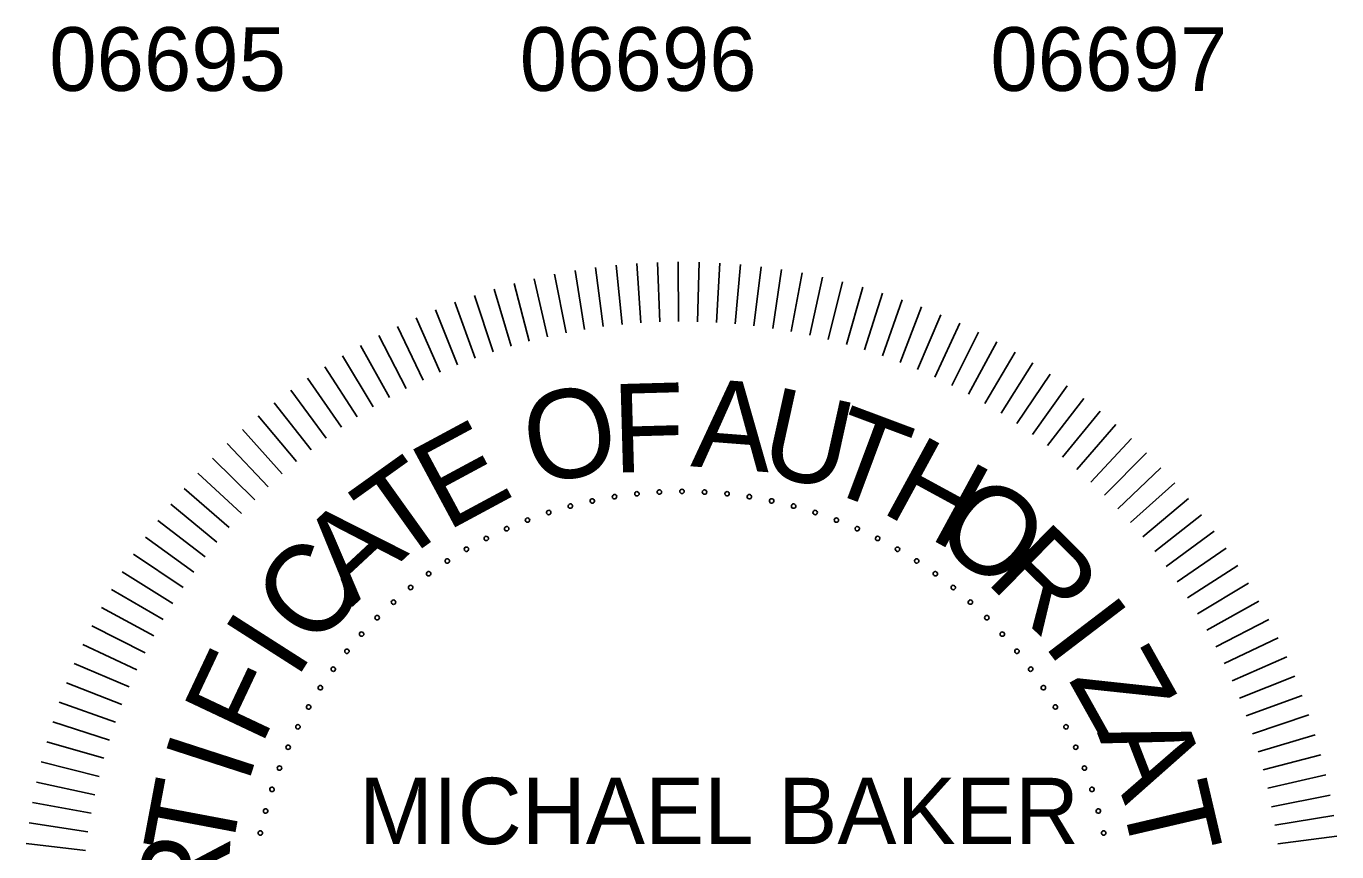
# Model space of a CAD drawing. Extents: x -12863 to 18921, y -8840 to 11152.
# Drawn here: x 10556 to 13026, y -7462 to -5907 of the extents above; entities that cross this region are included whole.
import ezdxf

# ---------------------------------------------------------------- set-up
doc = ezdxf.new("R2010")
doc.units = 0
doc.layers.add('Level 47', color=7, linetype='Continuous')
doc.layers.add('Level 50', color=7, linetype='Continuous')

msp = doc.modelspace()

# ---------------------------------------------------------------- linework, layer by layer
at = {"layer": 'Level 47'}
for points in [[(11608.5, -6478.2), (11590.4, -6367.5)], [(11590.4, -6367.5), (11608.5, -6478.2)], [(11643.7, -6473), (11629, -6361.8)], [(11629, -6361.8), (11643.7, -6473)], [(11679.1, -6468.9), (11667.9, -6357.3)], [(11667.9, -6357.3), (11679.1, -6468.9)], [(11714.5, -6466), (11706.8, -6354)], [(11706.8, -6354), (11714.5, -6466)], [(11750, -6464.1), (11745.9, -6351.9)], [(11745.9, -6351.9), (11750, -6464.1)], [(11785.6, -6463.3), (11785, -6351.1)], [(11785, -6351.1), (11785.6, -6463.3)], [(11821.1, -6463.7), (11824, -6351.5)], [(11824, -6351.5), (11821.1, -6463.7)], [(11856.7, -6465.2), (11863.1, -6353.1)], [(11863.1, -6353.1), (11856.7, -6465.2)], [(11892.2, -6467.8), (11902.1, -6356)], [(11902.1, -6356), (11892.2, -6467.8)], [(11927.5, -6471.5), (11941, -6360)], [(11941, -6360), (11927.5, -6471.5)], [(11962.8, -6476.3), (11979.7, -6365.3)], [(11979.7, -6365.3), (11962.8, -6476.3)], [(11504.2, -6500.5), (11475.7, -6391.9)], [(11475.7, -6391.9), (11504.2, -6500.5)], [(11538.8, -6492), (11513.7, -6382.6)], [(11513.7, -6382.6), (11538.8, -6492)], [(11573.5, -6484.6), (11551.9, -6374.4)], [(11551.9, -6374.4), (11573.5, -6484.6)], [(11997.8, -6482.2), (12018.3, -6371.8)], [(12018.3, -6371.8), (11997.8, -6482.2)], [(12032.7, -6489.2), (12056.6, -6379.6)], [(12056.6, -6379.6), (12032.7, -6489.2)], [(12067.3, -6497.3), (12094.6, -6388.5)], [(12094.6, -6388.5), (12067.3, -6497.3)], [(11436, -6520.7), (11400.8, -6414.1)], [(11400.8, -6414.1), (11436, -6520.7)], [(11470, -6510), (11438.1, -6402.4)], [(11438.1, -6402.4), (11470, -6510)], [(12101.7, -6506.5), (12132.4, -6398.6)], [(12132.4, -6398.6), (12101.7, -6506.5)], [(12135.7, -6516.8), (12169.8, -6409.9)], [(12169.8, -6409.9), (12135.7, -6516.8)], [(11369.2, -6545.2), (11327.4, -6441)], [(11327.4, -6441), (11369.2, -6545.2)], [(11402.4, -6532.4), (11363.8, -6427)], [(11363.8, -6427), (11402.4, -6532.4)], [(12169.5, -6528.1), (12206.9, -6422.3)], [(12206.9, -6422.3), (12169.5, -6528.1)], [(12202.8, -6540.5), (12243.5, -6435.9)], [(12243.5, -6435.9), (12202.8, -6540.5)], [(11336.5, -6558.9), (11291.3, -6456.2)], [(11291.3, -6456.2), (11336.5, -6558.9)], [(12235.7, -6553.9), (12279.7, -6450.7)], [(12279.7, -6450.7), (12235.7, -6553.9)], [(12268.2, -6568.4), (12315.5, -6466.6)], [(12315.5, -6466.6), (12268.2, -6568.4)], [(11272.3, -6589.6), (11220.8, -6489.9)], [(11220.8, -6489.9), (11272.3, -6589.6)], [(11304.1, -6573.8), (11255.8, -6472.5)], [(11255.8, -6472.5), (11304.1, -6573.8)], [(12300.3, -6583.9), (12350.7, -6483.6)], [(12350.7, -6483.6), (12300.3, -6583.9)], [(11240.9, -6606.4), (11186.3, -6508.4)], [(11186.3, -6508.4), (11240.9, -6606.4)], [(12331.8, -6600.3), (12385.3, -6501.7)], [(12385.3, -6501.7), (12331.8, -6600.3)], [(11210.1, -6624.2), (11152.5, -6527.9)], [(11152.5, -6527.9), (11210.1, -6624.2)], [(12362.8, -6617.8), (12419.4, -6520.9)], [(12419.4, -6520.9), (12362.8, -6617.8)], [(12393.2, -6636.2), (12452.8, -6541.1)], [(12452.8, -6541.1), (12393.2, -6636.2)], [(11179.9, -6643), (11119.3, -6548.5)], [(11119.3, -6548.5), (11179.9, -6643)], [(12423, -6655.6), (12485.6, -6562.4)], [(12485.6, -6562.4), (12423, -6655.6)], [(11150.3, -6662.6), (11086.7, -6570.2)], [(11086.7, -6570.2), (11150.3, -6662.6)], [(12452.3, -6675.8), (12517.7, -6584.7)], [(12517.7, -6584.7), (12452.3, -6675.8)], [(11093, -6704.8), (11023.7, -6616.5)], [(11023.7, -6616.5), (11093, -6704.8)], [(11121.3, -6683.3), (11054.8, -6592.8)], [(12480.8, -6697), (12549.1, -6608)], [(12549.1, -6608), (12480.8, -6697)], [(11065.4, -6727.2), (10993.3, -6641.1)], [(10993.3, -6641.1), (11065.4, -6727.2)], [(12508.7, -6719.1), (12579.8, -6632.3)], [(12579.8, -6632.3), (12508.7, -6719.1)], [(11038.4, -6750.4), (10963.8, -6666.6)], [(10963.8, -6666.6), (11038.4, -6750.4)], [(12535.9, -6742.1), (12609.6, -6657.5)], [(12609.6, -6657.5), (12535.9, -6742.1)], [(12638.7, -6683.6), (12562.3, -6765.9)], [(12562.3, -6765.9), (12638.7, -6683.6)], [(11012.3, -6774.5), (10935, -6693.1)], [(10935, -6693.1), (11012.3, -6774.5)], [(12666.9, -6710.7), (12588, -6790.5)], [(12588, -6790.5), (12666.9, -6710.7)], [(10986.9, -6799.4), (10907.1, -6720.5)], [(10907.1, -6720.5), (10986.9, -6799.4)], [(12694.3, -6738.6), (12612.9, -6815.9)], [(12612.9, -6815.9), (12694.3, -6738.6)], [(10962.3, -6825.1), (10880, -6748.7)], [(10880, -6748.7), (10962.3, -6825.1)], [(10938.5, -6851.5), (10853.9, -6777.8)], [(10853.9, -6777.8), (10938.5, -6851.5)], [(12720.7, -6767.4), (12637, -6842)], [(12637, -6842), (12720.7, -6767.4)], [(10915.5, -6878.7), (10828.6, -6807.6)], [(10828.6, -6807.6), (10915.5, -6878.7)], [(12746.3, -6796.9), (12660.2, -6869)], [(12660.2, -6869), (12746.3, -6796.9)], [(10893.4, -6906.6), (10804.4, -6838.3)], [(10804.4, -6838.3), (10893.4, -6906.6)], [(12770.9, -6827.3), (12682.6, -6896.6)], [(12682.6, -6896.6), (12770.9, -6827.3)], [(12794.5, -6858.4), (12704.1, -6924.9)], [(12704.1, -6924.9), (12794.5, -6858.4)], [(10872.2, -6935.1), (10781.1, -6869.7)], [(10781.1, -6869.7), (10872.2, -6935.1)], [(10851.9, -6964.3), (10758.8, -6901.8)], [(10758.8, -6901.8), (10851.9, -6964.3)], [(12817.2, -6890.3), (12724.7, -6953.9)], [(12724.7, -6953.9), (12817.2, -6890.3)], [(10832.6, -6994.2), (10737.5, -6934.6)], [(10737.5, -6934.6), (10832.6, -6994.2)], [(12838.9, -6922.9), (12744.4, -6983.5)], [(12744.4, -6983.5), (12838.9, -6922.9)], [(12859.5, -6956.1), (12763.2, -7013.7)], [(12763.2, -7013.7), (12859.5, -6956.1)], [(10814.2, -7024.6), (10717.3, -6968)], [(10717.3, -6968), (10814.2, -7024.6)], [(10796.7, -7055.6), (10698.1, -7002.1)], [(10698.1, -7002.1), (10796.7, -7055.6)], [(12879, -6989.9), (12781, -7044.5)], [(12781, -7044.5), (12879, -6989.9)], [(10780.3, -7087.1), (10680, -7036.7)], [(10680, -7036.7), (10780.3, -7087.1)], [(12897.5, -7024.4), (12797.8, -7075.9)], [(12797.8, -7075.9), (12897.5, -7024.4)], [(12914.9, -7059.4), (12813.6, -7107.7)], [(12813.6, -7107.7), (12914.9, -7059.4)], [(10764.8, -7119.1), (10663, -7071.9)], [(10663, -7071.9), (10764.8, -7119.1)], [(10750.3, -7151.6), (10647.1, -7107.6)], [(10647.1, -7107.6), (10750.3, -7151.6)], [(12931.2, -7094.9), (12828.4, -7140.1)], [(12828.4, -7140.1), (12931.2, -7094.9)], [(12946.3, -7131), (12842.2, -7172.8)], [(12842.2, -7172.8), (12946.3, -7131)], [(10736.9, -7184.6), (10632.3, -7143.8)], [(10632.3, -7143.8), (10736.9, -7184.6)], [(10724.5, -7217.9), (10618.7, -7180.5)], [(10618.7, -7180.5), (10724.5, -7217.9)], [(12960.4, -7167.4), (12855, -7206)], [(12855, -7206), (12960.4, -7167.4)], [(12973.2, -7204.4), (12866.7, -7239.6)], [(12866.7, -7239.6), (12973.2, -7204.4)], [(10713.2, -7251.6), (10606.3, -7217.5)], [(10606.3, -7217.5), (10713.2, -7251.6)], [(10702.9, -7285.7), (10595, -7255)], [(10595, -7255), (10702.9, -7285.7)], [(12984.9, -7241.7), (12877.3, -7273.6)], [(12877.3, -7273.6), (12984.9, -7241.7)], [(12995.5, -7279.3), (12886.9, -7307.8)], [(12886.9, -7307.8), (12995.5, -7279.3)], [(10693.7, -7320), (10584.9, -7292.7)], [(10584.9, -7292.7), (10693.7, -7320)], [(10685.6, -7354.7), (10576, -7330.8)], [(10576, -7330.8), (10685.6, -7354.7)], [(13004.8, -7317.3), (12895.4, -7342.4)], [(12895.4, -7342.4), (13004.8, -7317.3)], [(13012.9, -7355.5), (12902.8, -7377.1)], [(12902.8, -7377.1), (13012.9, -7355.5)], [(10678.6, -7389.5), (10568.2, -7369.1)], [(10568.2, -7369.1), (10678.6, -7389.5)], [(13019.9, -7394), (12909.1, -7412.2)], [(12909.1, -7412.2), (13019.9, -7394)], [(10672.7, -7424.6), (10561.7, -7407.7)], [(10561.7, -7407.7), (10672.7, -7424.6)], [(10667.9, -7459.9), (10556.4, -7446.4)], [(10556.4, -7446.4), (10667.9, -7459.9)], [(13025.6, -7432.6), (12914.3, -7447.3)], [(12914.3, -7447.3), (13025.6, -7432.6)]]:
    msp.add_lwpolyline(points, dxfattribs=at)
for centre, start, end in [((11664.8, -6793.3), 9, 189), ((11707, -6787.8), 6, 186), ((11707, -6787.8), 186, 6), ((11749.4, -6784.5), 3, 183), ((11749.4, -6784.5), 183, 3), ((11791.9, -6783.3), 0, 180), ((11791.9, -6783.3), 180, 0), ((11834.4, -6784.5), 357, 177), ((11834.4, -6784.5), 177, 357), ((11876.8, -6787.8), 354, 174), ((11876.8, -6787.8), 174, 354), ((11918.9, -6793.3), 351, 171), ((11581.7, -6811), 15, 195), ((11581.7, -6811), 195, 15), ((11623, -6801.1), 12, 192), ((11623, -6801.1), 192, 12), ((11664.8, -6793.3), 189, 9), ((11918.9, -6793.3), 171, 351), ((11960.7, -6801.1), 168, 348), ((11960.7, -6801.1), 348, 168), ((12002.1, -6811), 165, 345), ((12002.1, -6811), 345, 165), ((11500.8, -6837.3), 21, 201), ((11500.8, -6837.3), 201, 21), ((11540.9, -6823.1), 18, 198), ((11540.9, -6823.1), 198, 18), ((12042.9, -6823.1), 162, 342), ((12042.9, -6823.1), 342, 162), ((12082.9, -6837.3), 159, 339), ((12082.9, -6837.3), 339, 159), ((11461.6, -6853.6), 24, 204), ((11461.6, -6853.6), 204, 24), ((12122.2, -6853.6), 156, 336), ((12122.2, -6853.6), 336, 156), ((11385.8, -6892.2), 30, 210), ((11423.2, -6871.9), 27, 207), ((11423.2, -6871.9), 207, 27), ((12160.6, -6871.9), 153, 333), ((12160.6, -6871.9), 333, 153), ((12198, -6892.2), 330, 150), ((11349.6, -6914.4), 33, 213), ((11349.6, -6914.4), 213, 33), ((11385.8, -6892.2), 210, 30), ((12198, -6892.2), 150, 330), ((12234.2, -6914.4), 147, 327), ((12234.2, -6914.4), 327, 147), ((11314.5, -6938.5), 36, 216), ((11314.5, -6938.5), 216, 36), ((12269.3, -6938.5), 144, 324), ((12269.3, -6938.5), 324, 144), ((11280.8, -6964.3), 39, 219), ((11280.8, -6964.3), 219, 39), ((12303, -6964.3), 141, 321), ((12303, -6964.3), 321, 141), ((11248.5, -6991.9), 42, 222), ((11248.5, -6991.9), 222, 42), ((12335.3, -6991.9), 138, 318), ((12335.3, -6991.9), 318, 138), ((11217.6, -7021.2), 45, 225), ((11217.6, -7021.2), 225, 45), ((12366.2, -7021.2), 135, 315), ((12366.2, -7021.2), 315, 135), ((11188.3, -7052.1), 48, 228), ((11188.3, -7052.1), 228, 48), ((12395.4, -7052.1), 132, 312), ((12395.4, -7052.1), 312, 132), ((11160.7, -7084.4), 51, 231), ((11160.7, -7084.4), 231, 51), ((12423, -7084.4), 129, 309), ((12423, -7084.4), 309, 129), ((11134.8, -7118.1), 54, 234), ((11134.8, -7118.1), 234, 54), ((12448.9, -7118.1), 126, 306), ((12448.9, -7118.1), 306, 126), ((11110.8, -7153.2), 57, 237), ((11110.8, -7153.2), 237, 57), ((12473, -7153.2), 123, 303), ((12473, -7153.2), 303, 123), ((11088.5, -7189.4), 60, 240), ((12495.2, -7189.4), 300, 120), ((11088.5, -7189.4), 240, 60), ((12495.2, -7189.4), 120, 300), ((11068.3, -7226.8), 63, 243), ((11068.3, -7226.8), 243, 63), ((12515.5, -7226.8), 117, 297), ((12515.5, -7226.8), 297, 117), ((11050, -7265.2), 66, 246), ((11050, -7265.2), 246, 66), ((12533.8, -7265.2), 114, 294), ((12533.8, -7265.2), 294, 114), ((11033.7, -7304.4), 69, 249), ((11033.7, -7304.4), 249, 69), ((12550.1, -7304.4), 111, 291), ((12550.1, -7304.4), 291, 111), ((11019.5, -7344.5), 72, 252), ((11019.5, -7344.5), 252, 72), ((12564.3, -7344.5), 108, 288), ((12564.3, -7344.5), 288, 108), ((11007.4, -7385.3), 75, 255), ((11007.4, -7385.3), 255, 75), ((12576.4, -7385.3), 105, 285), ((12576.4, -7385.3), 285, 105), ((10997.5, -7426.6), 78, 258), ((10997.5, -7426.6), 258, 78), ((12586.3, -7426.6), 102, 282), ((12586.3, -7426.6), 282, 102)]:
    msp.add_arc(centre, 4.17, start, end, dxfattribs=at)

# ---------------------------------------------------------------- texts
for s, rotation, p in [('O', 10.7295, (11510.3, -6772.2)), ('F', 1.5867, (11662.6, -6748.2)), ('A', 355.5955, (11807.1, -6735.9)), ('U', 347.5481, (11933.2, -6747.8)), ('T', 339.5007, (12049.5, -6775.6)), ('E', 28.279, (11348.5, -6859.6)), ('H', 331.4533, (12162.6, -6820.2)), ('T', 35.5725, (11255.4, -6924.1)), ('O', 323.4059, (12258.3, -6872.9)), ('A', 42.8659, (11170.8, -7001.1)), ('R', 315.3585, (12361.5, -6951.9)), ('C', 50.1594, (11100.6, -7084.4)), ('I', 307.3112, (12469.9, -7069.3)), ('I', 57.4529, (11064.4, -7140.1)), ('F', 64.7464, (10999, -7264.8)), ('Z', 299.2638, (12518.8, -7137.2)), ('I', 72.0398, (10973.2, -7338)), ('A', 291.2164, (12573.5, -7237.5)), ('T', 79.3333, (10940.1, -7481.6)), ('T', 283.169, (12617.1, -7355.4)), ('R', 86.6268, (10932.4, -7591.8))]:
    msp.add_text(s, height=166.7, rotation=rotation, dxfattribs=at).set_placement(p)
msp.add_text('MICHAEL BAKER', height=125.016, dxfattribs=at).set_placement((11183.6, -7447.7))
at = {"layer": 'Level 50'}
for s, p in [('06695', (10599.8, -6028.9)), ('06696', (11486.3, -6028.9)), ('06697', (12372.9, -6028.9))]:
    msp.add_text(s, height=120, dxfattribs=at).set_placement(p)

doc.saveas('drawing.dxf')
